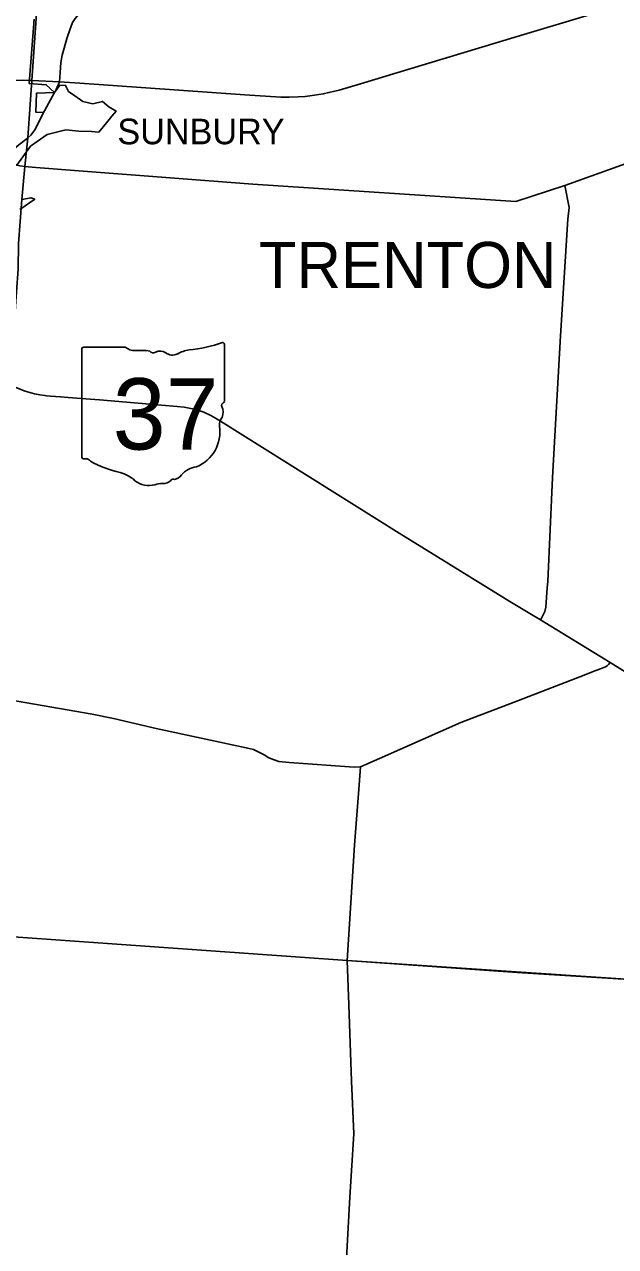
# Model space of a CAD drawing. Extents: x 1729596 to 1925846, y 659247 to 911751.
# Drawn here: x 1871056 to 1882614, y 797404 to 821273 of the extents above; entities that cross this region are included whole.
import ezdxf

# ---------------------------------------------------------------- set-up
doc = ezdxf.new("R2010")
doc.units = 0
for name, color, linetype in [('GM_X_City_Street', 7, 'Continuous'), ('GM_X_Corporation', 7, 'Continuous'), ('GM_X_Corporation_Text', 7, 'Continuous'), ('GM_X_County_Road', 7, 'Continuous'), ('GM_X_State_Route', 7, 'Continuous'), ('GM_X_State_Shield', 7, 'Continuous'), ('GM_X_Township', 7, 'Continuous'), ('GM_X_Township_Road', 7, 'Continuous'), ('GM_X_Township_Text', 7, 'Continuous'), ('GM_X_US_Route', 7, 'Continuous')]:
    doc.layers.add(name, color=color, linetype=linetype)

msp = doc.modelspace()

# ---------------------------------------------------------------- linework, layer by layer
at = {"layer": 'GM_X_City_Street'}
for points in [[(1871110, 819046), (1871124, 819057), (1871182, 819113), (1871265, 819220), (1871428, 819552), (1871447, 819585), (1871645, 819941), (1871647, 819944), (1871670, 819986), (1871678, 820004)], [(1871428, 819552), (1871278, 819563), (1871294, 819932), (1871647, 819944)], [(1870615, 818642), (1870639, 818661), (1870950, 818924), (1871110, 819046)]]:
    msp.add_lwpolyline(points, dxfattribs=at)
at = {"layer": 'GM_X_Corporation'}
for points in [[(1871245, 821376), (1871152, 820118), (1871483, 820096), (1871642, 819946), (1871748, 820085), (1871861, 820081), (1871921, 819965), (1872043, 819876), (1872199, 819766), (1872392, 819723), (1872582, 819770), (1872706, 819663), (1872848, 819582), (1872764, 819484), (1872661, 819350), (1872513, 819172), (1872369, 819183), (1872118, 819190), (1871863, 819214), (1871502, 819125), (1871177, 818898), (1870906, 818525)], [(1871003, 817857), (1871186, 817888), (1871257, 817859), (1870965, 817659)]]:
    msp.add_lwpolyline(points, dxfattribs=at)
at = {"layer": 'GM_X_County_Road'}
for points in [[(1871742, 820151), (1871742, 820151), (1871754, 820333), (1871771, 820532), (1871780, 820600), (1871796, 820672), (1871893, 821017), (1871942, 821170), (1871996, 821311), (1872051, 821390), (1872132, 821486), (1872206, 821558), (1872281, 821630), (1872352, 821694), (1872457, 821804), (1872502, 821861), (1872537, 821910), (1872571, 821965), (1872610, 822031), (1872673, 822132), (1872724, 822198)], [(1871678, 820004), (1871742, 820151)], [(1871277, 818480), (1872206, 818406), (1875525, 818156), (1880663, 817814), (1881619, 818131), (1884362, 819111), (1887858, 818871), (1889457, 818761), (1891623, 818604), (1892346, 818560), (1895326, 818344), (1897532, 818224), (1897769, 818211), (1897801, 818204), (1897822, 818179)], [(1870866, 818536), (1870906, 818522), (1870968, 818509), (1871065, 818497), (1871277, 818480)], [(1870615, 808110), (1872380, 807804), (1872796, 807716), (1873633, 807525), (1875394, 807147), (1875535, 807109), (1875625, 807069), (1875741, 807006), (1875837, 806950), (1875938, 806910), (1876028, 806878), (1876232, 806859), (1877504, 806767), (1877627, 806773), (1878001, 806934), (1879588, 807637), (1880629, 808038), (1881916, 808534), (1882228, 808657), (1882321, 808690), (1882416, 808728), (1882452, 808749), (1882473, 808770), (1882507, 808811)], [(1877369, 802994), (1877508, 805242), (1877600, 806419), (1877627, 806773)], [(1869930, 803545), (1869936, 803538), (1870008, 803514), (1877369, 802994)], [(1877332, 796811), (1877420, 798367), (1877499, 799608), (1877454, 800633), (1877398, 802125), (1877369, 802994)]]:
    msp.add_lwpolyline(points, dxfattribs=at)
at = {"layer": 'GM_X_State_Route'}
for points in [[(1870207, 814697), (1870211, 814693), (1870271, 814626), (1870352, 814549), (1870443, 814463), (1870476, 814436), (1870628, 814325), (1870779, 814239), (1870889, 814182), (1871068, 814112), (1871253, 814061), (1871361, 814039), (1871455, 814026)], [(1871455, 814026), (1871491, 814021), (1871569, 814014), (1871759, 814000), (1871910, 813989), (1872340, 813955), (1872527, 813939), (1873053, 813896), (1874044, 813812), (1874182, 813797), (1874274, 813782), (1874381, 813759), (1874562, 813699), (1874700, 813634), (1874793, 813581), (1874892, 813523), (1878383, 811338), (1880549, 810005), (1880810, 809846), (1880939, 809769), (1881144, 809643), (1882507, 808811), (1883124, 808426)]]:
    msp.add_lwpolyline(points, dxfattribs=at)
at = {"layer": 'GM_X_State_Shield'}
for p, q in [((1872182, 814935), (1872182, 812822)), ((1872182, 814935), (1872182, 812822)), ((1873024, 814972), (1872209, 814972)), ((1873024, 814972), (1872209, 814972)), ((1874966, 813919), (1874966, 815024)), ((1874966, 813919), (1874966, 815024)), ((1874966, 813919), (1874966, 813919)), ((1874966, 813919), (1874966, 813919))]:
    msp.add_line(p, q, dxfattribs=at)
for centre, radius, start, end in [((1872213, 814940), 32.3, 98.1301, 188.1301), ((1872213, 814940), 32.3, 98.1301, 188.1301), ((1873219, 815217), 313, 231.6195, 271.1119), ((1873219, 815217), 313, 231.6195, 271.1119), ((1873322, 813785), 1123, 80.4867, 94.9883), ((1873322, 813785), 1123, 80.4867, 94.9883), ((1874351, 814326), 594, 97.3462, 120.7689), ((1874351, 814326), 594, 97.3462, 120.7689), ((1873974, 817853), 2953, 275.8445, 288.9065), ((1873974, 817853), 2953, 275.8445, 288.9065), ((1874935, 815029), 31, 351.8621, 97.738), ((1874935, 815029), 31, 351.8621, 97.738), ((1873577, 814951), 90.3, 219.7921, 297.1024), ((1873577, 814951), 90.3, 219.7921, 297.1024), ((1873710, 814707), 188, 54.4667, 119.1411), ((1873710, 814707), 188, 54.4667, 119.1411), ((1873952, 815042), 226, 233.8562, 294.8282), ((1873952, 815042), 226, 233.8562, 294.8282), ((1874959, 813838), 48, 107.944, 210.337), ((1874959, 813838), 48, 107.944, 210.337), ((1874654, 813698), 288, 340.033, 23.6496), ((1874654, 813698), 288, 340.033, 23.6496), ((1874933, 813914), 33.2, 289.6038, 7.7341), ((1874933, 813914), 33.2, 289.6038, 7.7341), ((1875077, 813456), 210, 136.8065, 186.9296), ((1875077, 813456), 210, 136.8065, 186.9296), ((1874139, 813315), 739, 292.3089, 8.9858), ((1874139, 813315), 739, 292.3089, 8.9858), ((1872214, 812818), 32.5, 171.9584, 258.3066), ((1872214, 812818), 32.5, 171.9584, 258.3066), ((1872219, 813034), 248, 267.339, 280.6039), ((1872219, 813034), 248, 267.339, 280.6039), ((1872269, 812700), 89.5, 29.7484, 93.2717), ((1872269, 812700), 89.5, 29.7484, 93.2717), ((1873400, 814599), 2132, 240.4129, 257.1985), ((1873400, 814599), 2132, 240.4129, 257.1985), ((1874451, 812229), 404, 94.4031, 142.5768), ((1874451, 812229), 404, 94.4031, 142.5768), ((1872764, 811873), 667, 47.1842, 75.836), ((1872764, 811873), 667, 47.1842, 75.836), ((1873486, 812690), 423, 230.7004, 286.2918), ((1873486, 812690), 423, 230.7004, 286.2918), ((1873731, 811959), 348, 85.6951, 111.2099), ((1873731, 811959), 348, 85.6951, 111.2099), ((1873761, 812531), 226, 268.777, 315.5493), ((1873761, 812531), 226, 268.777, 315.5493), ((1873965, 812327), 63.5, 65.7517, 132.6484), ((1873965, 812327), 63.5, 65.7517, 132.6484), ((1873938, 812617), 239, 282.8732, 323.2771), ((1873938, 812617), 239, 282.8732, 323.2771)]:
    msp.add_arc(centre, radius, start, end, dxfattribs=at)
at = {"layer": 'GM_X_Township'}
msp.add_lwpolyline([(1896867, 801714), (1892288, 802025), (1891297, 802083), (1891221, 802088), (1891165, 802089), (1883392, 802588), (1877369, 802994), (1870008, 803514), (1870309, 808163), (1870779, 814239), (1870903, 816053), (1870933, 816495), (1870943, 816996), (1871003, 817857), (1871065, 818497), (1871124, 819057), (1871199, 820179), (1871965, 831096)], dxfattribs=at)
at = {"layer": 'GM_X_Township_Road'}
for points in [[(1881144, 809643), (1881165, 809679), (1881231, 809806), (1881247, 809894), (1881278, 810269), (1881288, 810392), (1881379, 812426), (1881535, 815194), (1881680, 817467), (1881704, 817701), (1881619, 818131)], [(1877369, 802994), (1880691, 802757), (1883392, 802588)]]:
    msp.add_lwpolyline(points, dxfattribs=at)
at = {"layer": 'GM_X_US_Route'}
for points in [[(1871153, 820180), (1871199, 820179), (1871742, 820151), (1872137, 820124), (1875367, 819897), (1876072, 819853), (1876232, 819852), (1876406, 819857), (1876545, 819867), (1876727, 819890), (1876899, 819917), (1877009, 819941), (1877209, 819989), (1877624, 820113), (1878554, 820394), (1880687, 821035), (1883192, 821790)], [(1869772, 820024), (1869935, 820064), (1870218, 820115), (1870358, 820133), (1870708, 820169), (1871013, 820182), (1871153, 820180)]]:
    msp.add_lwpolyline(points, dxfattribs=at)

# ---------------------------------------------------------------- texts
at = {"layer": 'GM_X_Corporation_Text'}
msp.add_text('SUNBURY', height=500, rotation=0, dxfattribs=at).set_placement((1872874, 818933))
at = {"layer": 'GM_X_State_Shield'}
msp.add_text('37', height=1392.2, dxfattribs=at).set_placement((1872782, 812971))
msp.add_text('37', height=1392.2, dxfattribs=at).set_placement((1872782, 812971))
at = {"layer": 'GM_X_Township_Text'}
msp.add_text('TRENTON', height=900, rotation=0, dxfattribs=at).set_placement((1875642, 816126))

doc.saveas('drawing.dxf')
